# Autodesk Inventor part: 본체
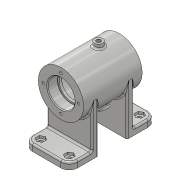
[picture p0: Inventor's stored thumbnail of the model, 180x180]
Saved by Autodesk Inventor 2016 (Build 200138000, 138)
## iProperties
Created: 2017-02
Part Number: 본체
Material: 알루미늄 6061
Document SubType Name: Modeling
Designer: H
Density: 2.7 g/cm^3
Appearance: 알루미늄 - 평지
Mass: 353.37 g
Surface Area: 426.421 cm^2
Volume: 130.878 cm^3
Author: H
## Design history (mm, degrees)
sketch "스케치1"
  geometry: L1 (-27, -52)-(27, -52); L2 (27, 52)-(-27, 52); L3 (-27, -52)-(27, 52); L4 (27, -52)-(-27, 52); L5 (-27, -17)-(27, -17); L6 (27, 17)-(-27, 17); L7 (-27, -17)-(27, 17); L8 (27, -17)-(-27, 17); L9 (27, -52)-(27, -17); L10 (27, 17)-(27, 52); L11 (-27, 52)-(-27, 17); L12 (-27, -17)-(-27, -52); 1 further point
  constraints: 24 end point, 6 parallel, 4 midpoint, 2 horizontal, 2 perpendicular
  dimensions: "d4" = 34 distance between parallel lines of L5 L6; "d5" = 54 distance between parallel lines of L10 L11; "d6" = 17 distance from line of point (0, 0) L6; "d7" = 52 vertical distance of point (0, 0) L2.end; "d8" = 27 distance from line of L10 point (0, 0)
extrude "돌출1" new body sketch "스케치1" distance "d9" = 8; taper "d10" = 0 deg
sketch "스케치2"
  geometry: L1 (52, 0)-(17, 0) reference; L2 (17, 0)-(17, 8) reference; L3 (52, 8)-(17, 8) reference; L4 (52, 0)-(52, 8) reference; L5 (-17, 0)-(-52, 0) reference; L6 (-52, 0)-(-52, 8) reference; L7 (-17, 8)-(-52, 8) reference; L8 (-17, 0)-(-17, 8) reference; L9 (17, 0)-(25, 0); L10 (25, 0)-(25, 60); L11 (25, 60)-(17, 60); L12 (17, 60)-(17, 0); L13 (-17, 0)-(-25, 0); L14 (-25, 0)-(-25, 60); L15 (-25, 60)-(-17, 60); L16 (-17, 60)-(-17, 0); 1 further point
  constraints: 16 end point, 4 parallel, 2 horizontal, 2 perpendicular
  dimensions: "d11" = 8 distance of L11.end L10.end; "d12" = 60 distance of L9.end L10.end; "d13" = 8 distance of L14.end L15.end; "d14" = 60 distance of L13.end L14.end
extrude "돌출2" join sketch "스케치2" stored distance "d15" = 54; taper "d16" = 0 deg
sketch "스케치3"
  geometry: L1 (27, 60)-(-27, 60) reference; C1 r 27 at (0, 60); 2 further points
  constraints: 1 centre point, 1 coincident, 1 midpoint
  dimensions: "d17" = 54 diameter of C1
extrude "돌출3" join sketch "스케치3" stored distance "d18" = 70; taper "d19" = 0 deg
sketch "스케치4"
  geometry: L1 (17, 60)-(25, 60) reference; L2 (17, 60)-(17, 60) reference; L3 (25, 60)-(17, 60) reference; L4 (25, 60)-(25, 60) reference; L5 (-25, 60)-(-25, 60) reference; L6 (-17, 60)-(-25, 60) reference; L7 (-17, 60)-(-17, 60) reference; L8 (-25, 60)-(-17, 60) reference; L9 (-35, 87)-(-35, 33) reference; L10 (35, 33)-(35, 87) reference; L11 (15, 82)-(10, 82); L12 (10, 82)-(10, 92); L13 (10, 92)-(15, 92); L14 (15, 92)-(15, 82); 1 further point
  constraints: 8 end point, 2 parallel, 1 horizontal, 1 perpendicular
  dimensions: "d20" = 5 distance of L12.end L13.end; "d21" = 5 distance from line of L10.end L13; "d22" = 25 distance from line of L12 L10.end; "d23" = 10 distance of L13.end L11.start
revolve "회전1" sketch "스케치4" stored, may be unused: angle "d24" = 90 deg
sketch "스케치5"
  geometry: L1 (0, 60)-(-16.339, 34.84); L2 (0, 60)-(0, 33); L3 (-21.371, 38.108)-(-17.014, 44.817); L4 (-21.371, 38.108)-(-16.339, 34.84); L5 (-17.014, 44.817)-(-11.982, 41.549); 1 further point
  constraints: 10 end point, 2 perpendicular, 1 point on line, 1 vertical, 1 vertical alignment, 1 other
  dimensions: "d25" = 30 distance of L1.start L1.end; "d26" = 33 deg angle of L1 L2; "d27" = 6 distance between parallel lines of L1 L3; "d29" = 8 distance of L3.start L3.end
revolve "회전2" sketch "스케치5" stored, may be unused: angle "d30" = 90 deg
sketch "스케치6"
  geometry: L1 (35, 33)-(35, 87) reference; L2 (-35, 87)-(-35, 33) reference; L3 (35, 60)-(-35, 60); L4 (35, 60)-(35, 76); L5 (35, 76)-(23, 76); L6 (23, 76)-(23, 74); L7 (23, 74)-(20, 74); L8 (20, 74)-(20, 82); L9 (20, 82)-(-20, 82); L10 (-20, 82)-(-20, 74); L11 (-20, 74)-(-23, 74); L12 (-23, 74)-(-23, 76); L13 (-23, 76)-(-35, 76); L14 (-35, 76)-(-35, 60); 1 further point
  constraints: 24 end point, 9 perpendicular, 2 midpoint, 2 point on line, 1 vertical
  dimensions: "d31" = 16 distance of L3.start L4.end; "d32" = 12 distance of L4.end L5.end; "d33" = 3 distance of L6.end L7.end; "d34" = 40 distance of L8.end L9.end; "d35" = 3 distance of L10.end L11.end; "d36" = 32 diameter of L13 L3; "d37" = 28 diameter of L11 L3; "d38" = 28 diameter of L7 L3; "d39" = 44 diameter of L9 L3
revolve "회전3" sketch "스케치6" stored, may be unused: angle "d40" = 90 deg
sketch "스케치7"
  geometry: C1 r 16 at (0, 0) reference; C2 r 27 at (0, 0) reference; 2 further points
  dimensions: "d41" = 21 distance of C1.centre point (0, -21); "d42" = 0 horizontal distance of C1.centre point (0, -21)
hole "구멍1" sketch "스케치7" at (0, -21) diameter "d43" = 3.242; stored, may be unused: countersink angle "d47" = 90 deg, drill point angle "d49" = 118 deg; dims "d44" = 8, "d45" = 4, "d46" = 2, "d48" = 10
sketch "스케치8"
  geometry: C1 r 5 at (0, 0) reference; 2 further points
  constraints: 1 coincident
hole "구멍2" sketch "스케치8" at (0, 0) diameter "d53" = 5.188; stored, may be unused: countersink angle "d57" = 90 deg, drill point angle "d59" = 118 deg; dims "d54" = 15, "d55" = 4, "d56" = 2, "d58" = 19
sketch "스케치9"
  geometry: C1 r 6 at (0, 0) reference; 2 further points
  constraints: 1 coincident
hole "구멍3" sketch "스케치9" at (0, 0) diameter "d60" = 5.188; stored, may be unused: countersink angle "d64" = 90 deg, drill point angle "d66" = 118 deg; dims "d61" = 15, "d62" = 4, "d63" = 2, "d65" = 19
sketch "스케치10"
  geometry: L1 (17, 47.196)-(21.5, 44.598); L2 (21.5, 44.598)-(21.5, 39.402); L3 (21.5, 39.402)-(17, 36.804); L4 (17, 36.804)-(12.5, 39.402); L5 (12.5, 39.402)-(12.5, 44.598); L6 (12.5, 44.598)-(17, 47.196); L7 (27, 52)-(-27, 52) reference; C1 r 4.5 at (17, 42); 2 further points
  constraints: 12 end point, 1 centre point, 1 coincident, 1 tangent, 13 other
  dimensions: "d67" = 9 diameter of C1; "d68" = 90 deg angle of L2 L7; "d69" = 42 vertical distance of point (17, 42) point (0, 0); "d70" = 17 horizontal distance of point (17, 42) point (0, 0)
extrude "돌출4" cut sketch "스케치10" distance "d71" = 3; taper "d72" = 0 deg
sketch "스케치11"
  geometry: C1 r 2.5 at (17, 42); 1 further point
  constraints: 1 centre point
  dimensions: "d73" = 5 diameter of C1; "d74" = 17 horizontal distance of point (0, 0) C1.centre; "d75" = 42 vertical distance of C1.centre point (0, 0)
extrude "돌출5" cut sketch "스케치11" stored distance "d76" = 3; taper "d77" = 0 deg
fillet "모깎기1" dims "d84" = 10
chamfer "모따기1" distance "d85" = 1; stored, may be unused: second distance "d86" = 2, angle "d87" = 45 deg
fillet "모깎기2" dims "d88" = 0.3
fillet "모깎기3" dims "d89" = 2
fillet "모깎기4" dims "d90" = 2
fillet "모깎기5" dims "d91" = 2
node "작업 평면1"
sketch "스케치12"
  geometry: L1 (-35, 87)-(-35, 33) reference; 2 further points
  constraints: 1 other
  dimensions: "d93" = 35 distance from line of point (0, 60) L1; "d94" = 27 vertical distance of point (0, 60) L1.start
feature "엠보싱1" sketch "스케치12" dims "d95" = 0.5, "d96" = 0
node "솔리드1"
pattern_circular "원형 패턴1" dims angle "d51" = 360 deg
mirror "대칭1"
pattern_linear "직사각형 패턴1" dims "d80" = 84, "d83" = 34
node "투영된 루프1"
node "투영된 루프2"
node "투영된 루프3"
node "투영된 루프4"
node "투영된 루프5"
other parameters: "d92" = -75
